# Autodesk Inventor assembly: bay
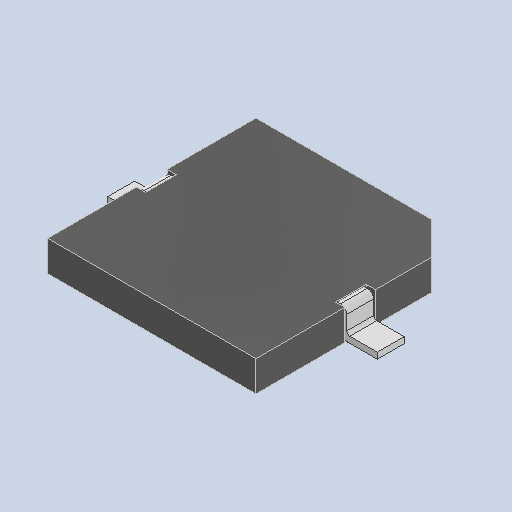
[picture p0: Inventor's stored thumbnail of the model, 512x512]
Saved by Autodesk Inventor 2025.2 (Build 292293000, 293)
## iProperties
Created: 2025-04
Part Number: bay
Description: PART--DESC
Document SubType Name: Assembly
Designer: BennF
Author: BennF
Revision Number: NONE
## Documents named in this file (3)
- C:\Users\BennF\Nextcloud\Benutzer\CNC JarBeRi\existing parts\Electronics\RepRap A4988 Shied (USE WITHOUT ARDUINO)\reprap-a4988-1.snapshot.1\RepRap\RepRap\bay_5.iam
- C:\Users\BennF\Nextcloud\Benutzer\CNC JarBeRi\existing parts\Electronics\RepRap A4988 Shied (USE WITHOUT ARDUINO)\reprap-a4988-1.snapshot.1\RepRap\RepRap\bay Geometry.ipt
- C:\Users\BennF\Nextcloud\Benutzer\CNC JarBeRi\existing parts\Electronics\RepRap A4988 Shied (USE WITHOUT ARDUINO)\reprap-a4988-1.snapshot.1\RepRap\RepRap\pin14.ipt
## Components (2 placed, 2 different names)
1. bay Geometry
2. pin14
